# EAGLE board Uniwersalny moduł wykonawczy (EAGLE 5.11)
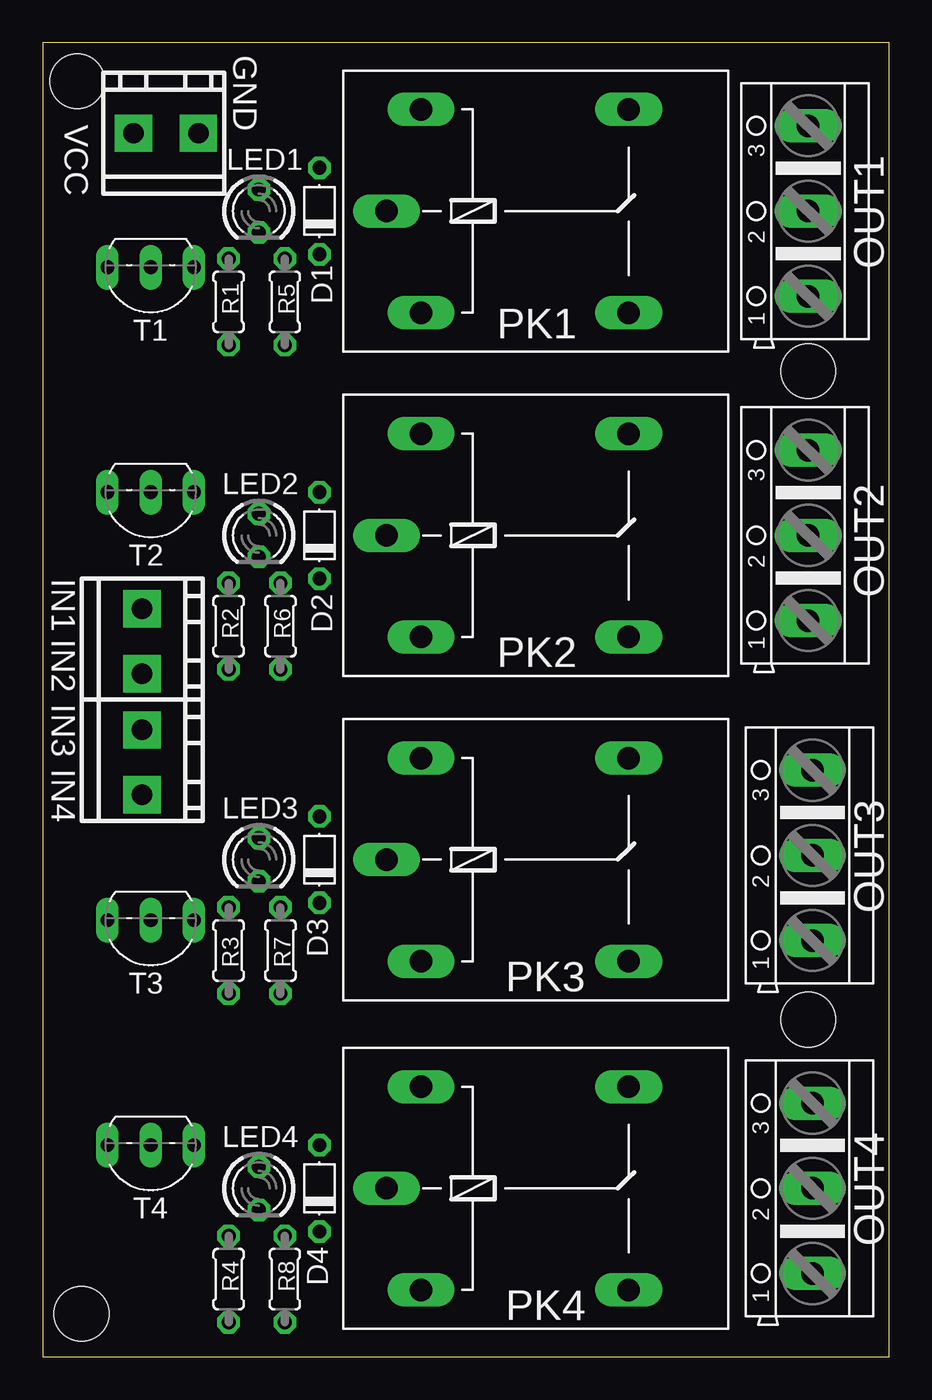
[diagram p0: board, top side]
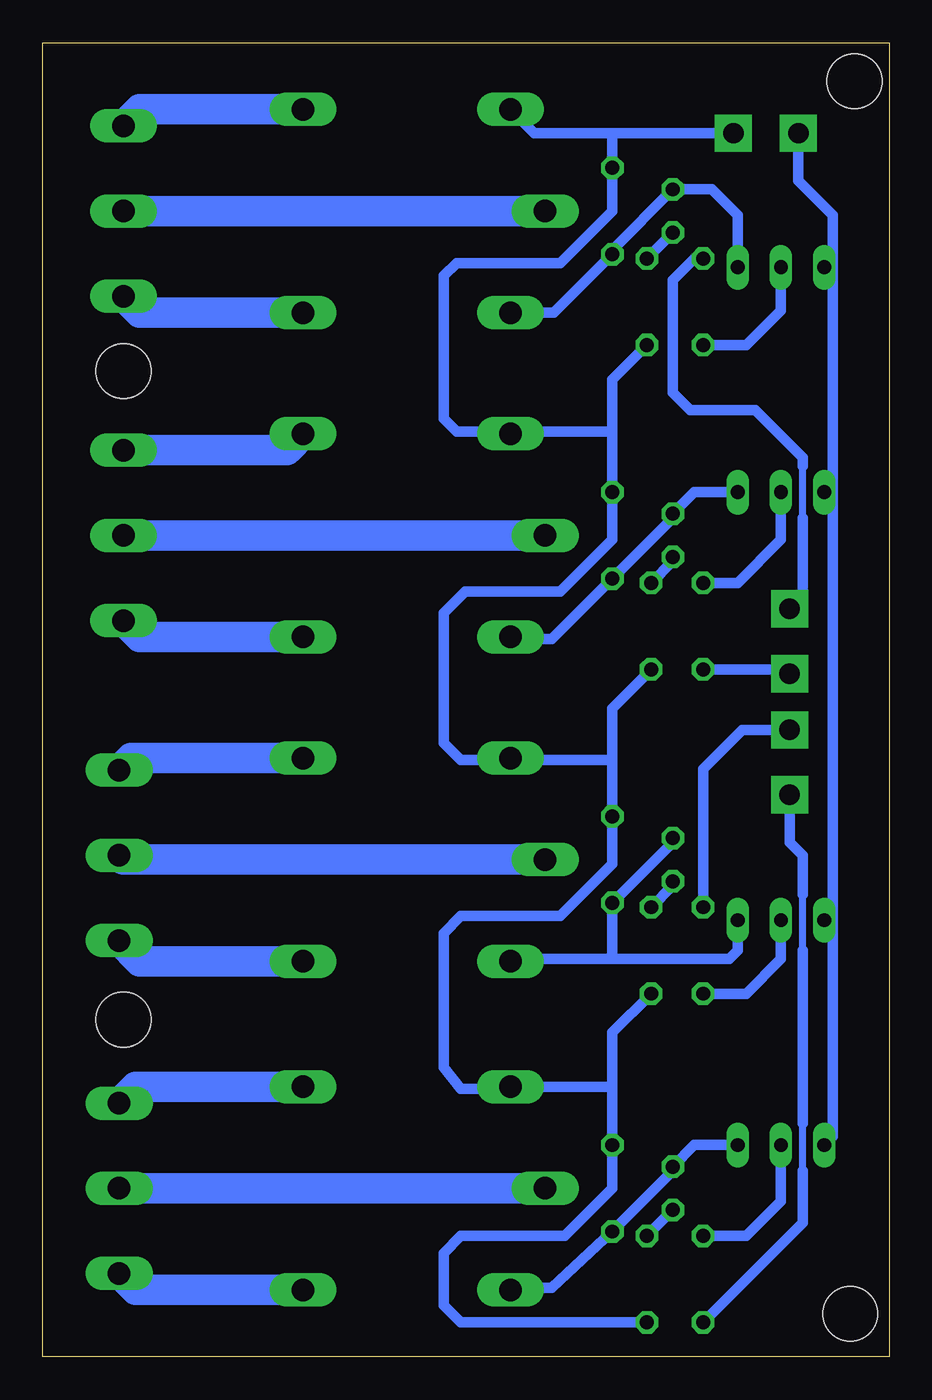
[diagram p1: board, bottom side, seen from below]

Size 49.71 x 77.21 mm. Coordinates in mm from the lower left corner, seen from the top.
Outline: 0,0 49.71,0 49.71,77.21 0,77.21 0,0
Copper layers (1*16): Top 0.035mm / dielectric 1.5mm / Bottom 0.035mm
Design rules "default": minimum track width 10mil, minimum drill 24mil, track to track 8mil, track to pad 8mil, pad to pad 8mil, via to via 8mil, smd to smd 8mil, copper to edge 40mil, drill to drill 8mil, minimum pad ring 10mil, minimum via ring 8mil, stop-mask expansion 4mil, vias tented up to drill 0mil, thermal gap 10mil
Holes 3.2 mm at 44.96,57.91 44.96,19.81 2.29,2.54 2.03,74.93

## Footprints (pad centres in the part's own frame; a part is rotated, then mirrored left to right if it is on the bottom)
ARK2/300 = drill 1.2 pad 2.184 square: 1 -2.54,0; 2 1.27,0
D-5 = drill 0.813 octagon: A 2.54,0; C -2.54,0
LED3MM = drill 0.813 octagon: A -1.27,0; K 1.27,0
AK500/3 = drill 1.321 long: 1 -5.004,0; 2 0,0; 3 5.004,0
G5LE = drill 1.321 long: 1 -7.493,-5.969; 2 -7.493,5.969; O 4.699,5.969; P -9.525,0; S 4.699,-5.969
0204/5 = drill 0.813 octagon: 1 -2.54,0; 2 2.54,0
TO92-EBC = drill 0.813 long: B 0,-1.27; C -2.54,-1.27; E 2.54,-1.27

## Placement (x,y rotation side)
CON1  ARK2/300  [ARK2/300]  7.87,71.88 0 top
CON2  ARK2/300  [ARK2/300]  5.84,34.29 270 top
CON3  ARK2/300  [ARK2/300]  5.84,41.4 270 top
D1  [D-5]  16.26,67.31 90 top
D2  [D-5]  16.26,48.26 90 top
D3  [D-5]  16.26,29.21 90 top
D4  [D-5]  16.26,9.91 90 top
LED1  [LED3MM]  12.7,67.31 270 top
LED2  [LED3MM]  12.7,48.26 270 top
LED3  [LED3MM]  12.7,29.21 270 top
LED4  [LED3MM]  12.7,9.91 270 top
OUT1  [AK500/3]  44.96,67.31 90 top
OUT2  [AK500/3]  44.96,48.26 90 top
OUT3  [AK500/3]  45.21,29.46 90 top
OUT4  [AK500/3]  45.21,9.91 90 top
PK1  G5LE  [G5LE]  29.72,67.31 0 top
PK2  G5LE  [G5LE]  29.72,48.26 0 top
PK3  G5LE  [G5LE]  29.72,29.21 0 top
PK4  G5LE  [G5LE]  29.72,9.91 0 top
R1  [0204/5]  10.92,61.98 270 top
R2  [0204/5]  10.92,42.93 90 top
R3  [0204/5]  10.92,23.88 270 top
R4  [0204/5]  10.92,4.57 90 top
R5  [0204/5]  14.22,61.98 90 top
R6  [0204/5]  13.97,42.93 90 top
R7  [0204/5]  13.97,23.88 90 top
R8  [0204/5]  14.22,4.57 90 top
T1  BC557B  [TO92-EBC]  6.35,62.74 180 top
T2  BC557B  [TO92-EBC]  6.35,49.53 180 top
T3  BC557B  [TO92-EBC]  6.35,24.38 180 top
T4  BC557B  [TO92-EBC]  6.35,11.18 180 top

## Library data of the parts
CON1-CON3 = ds_lib_eagle
D1-D4 = diode
LED1-LED4 = led
OUT1-OUT4 = con-ptr500; OC_FARNELL: unknown; OC_NEWARK: unknown
PK1-PK4 = relay; OC_FARNELL: unknown; OC_NEWARK: unknown
R1-R8 = rcl
T1-T4 = transistor-pnp

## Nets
GND: CON1.2 D1.A D2.A D3.A D4.A PK1.2 PK2.2 PK3.2 PK4.2 R5.1 R6.1 R7.1 R8.1
N$1: OUT1.2 PK1.P
N$2: OUT1.3 PK1.O
N$3: OUT1.1 PK1.S
N$4: R1.2 T1.B
N$5: LED1.K R5.2
N$6: D1.C LED1.A PK1.1 T1.C
N$7: OUT3.2 PK3.P
N$8: CON3.1 R1.1
N$9: CON3.2 R2.1
N$10: OUT2.2 PK2.P
N$11: OUT2.3 PK2.O
N$12: OUT2.1 PK2.S
N$13: LED2.K R6.2
N$14: D2.C LED2.A PK2.1 T2.C
N$15: OUT3.3 PK3.O
N$16: R2.2 T2.B
N$17: CON2.1 R3.1
N$18: OUT3.1 PK3.S
N$19: LED3.K R7.2
N$20: D3.C LED3.A PK3.1 T3.C
N$21: R3.2 T3.B
N$22: CON2.2 R4.1
N$23: OUT4.2 PK4.P
N$24: OUT4.3 PK4.O
N$25: OUT4.1 PK4.S
N$26: LED4.K R8.2
N$27: D4.C LED4.A PK4.1 T4.C
N$28: R4.2 T4.B
VCC: CON1.1 T1.E T2.E T3.E T4.E

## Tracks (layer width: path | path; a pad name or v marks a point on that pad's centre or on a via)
GND
  Bottom 0.61: 16.26,71.88 CON1.2 | 16.26,71.88 20.83,71.88 PK1.2 | 16.26,71.88 D1.A 16.26,67.31 19.3,64.26 25.4,64.26 26.16,63.5 26.16,55.12 25.4,54.36 22.1,54.36 | R5.1 16.26,57.4 16.26,54.36 | 16.26,54.36 22.1,54.36 | 16.26,54.36 D2.A 16.26,48.01 19.3,44.96 24.89,44.96 26.16,43.69 26.16,36.07 25.15,35.05 22.35,35.05 PK3.2 22.1,35.05 16.26,35.05 | 22.1,54.36 PK2.2 | R8.1 25.15,2.03 26.16,3.05 26.16,6.1 25.15,7.11 19.05,7.11 16.26,9.91 D4.A 16.26,15.75 16.26,16 | 16.26,16 16.26,19.05 R7.1 | 16.26,16 16.38,15.88 PK4.2 22.35,15.75 25.15,15.75 26.16,17.02 26.16,24.89 25.15,25.91 19.3,25.91 16.26,28.96 D3.A 16.26,35.05 | R6.1 16.26,38.1 16.26,35.05
N$1
  Bottom 1.778: PK1.P OUT1.2
N$2
  Bottom 1.778: PK1.O 43.99,73.28 OUT1.3
N$3
  Bottom 1.778: PK1.S 43.99,61.34 OUT1.1
N$4
  Bottom 0.61: T1.B 6.35,61.47 8.38,59.44 R1.2
N$5
  Bottom 0.61: LED1.K R5.2
N$6
  Bottom 0.61: PK1.1 19.69,61.34 D1.C 16.26,65.02 LED1.A 10.41,68.58 8.89,67.06 T1.C
N$7
  Bottom 1.778: PK3.P 44.96,29.21 OUT3.2
N$8
  Bottom 0.406: 5.08,49.28 5.08,52.32
  Bottom 0.61: R1.1 11.43,64.52 12.7,63.25 12.7,56.64 11.68,55.63 7.87,55.63 5.08,52.83 5.08,52.32 | 5.08,49.28 5.08,44.7 CON3.1
N$9
  Bottom 0.61: R2.1 6.1,40.39 CON3.2
N$10
  Bottom 1.778: PK2.P OUT2.2
N$11
  Bottom 1.778: OUT2.3 35.38,53.26 PK2.O
N$12
  Bottom 1.778: PK2.S 43.99,42.29 OUT2.1
N$13
  Bottom 0.61: LED2.K 12.7,46.74 R6.2
N$14
  Bottom 0.61: T2.C 11.43,50.8 LED2.A 12.7,49.28 D2.C 19.81,42.16 22.1,42.16 PK2.1
N$15
  Bottom 1.778: PK3.O 44.5,35.18 OUT3.3
N$16
  Bottom 0.61: T2.B 6.35,48.01 8.89,45.47 R2.2
N$17
  Bottom 0.61: CON2.1 8.64,36.83 10.92,34.54 R3.1
N$18
  Bottom 1.778: PK3.S 43.99,23.24 OUT3.1
N$19
  Bottom 0.61: LED3.K 12.7,27.69 R7.2
N$20
  Bottom 0.61: LED3.A 12.7,30.23 D3.C 16.26,23.62 16.51,23.37 | PK3.1 22.1,23.37 16.51,23.37 | T3.C 8.89,23.88 9.4,23.37 16.51,23.37
N$21
  Bottom 0.61: T3.B 6.35,23.37 8.38,21.34 R3.2
N$22
  Bottom 0.406: 5.08,10.92 5.08,13.72 | 5.08,23.88 5.08,27.18
  Bottom 0.61: CON2.2 5.84,30.23 5.08,29.46 5.08,27.18 | R4.1 5.08,7.87 5.08,10.92 | 5.08,13.72 5.08,23.88
N$23
  Bottom 1.778: PK4.P OUT4.2
N$24
  Bottom 1.778: PK4.O 44.25,15.88 OUT4.3
N$25
  Bottom 1.778: PK4.S 44.25,3.94 OUT4.1
N$26
  Bottom 0.61: R8.2 LED4.K
N$27
  Bottom 0.61: T4.C 11.43,12.45 LED4.A 12.7,10.92 D4.C 19.81,4.06 22.1,4.06 PK4.1
N$28
  Bottom 0.61: R4.2 8.38,7.11 6.35,9.14 T4.B
VCC
  Bottom 0.61: CON1.1 5.33,69.09 3.3,67.06 3.3,64.01 | 3.3,25.4 3.3,12.95 T4.E | 3.3,25.4 3.3,50.8 | 3.3,50.8 3.3,64.01 | T3.E 3.56,25.65 3.3,25.4 | 3.3,50.8 T2.E | 3.3,64.01 T1.E

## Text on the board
tNames: GND | VCC | IN1 | IN2 | IN3 | IN4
